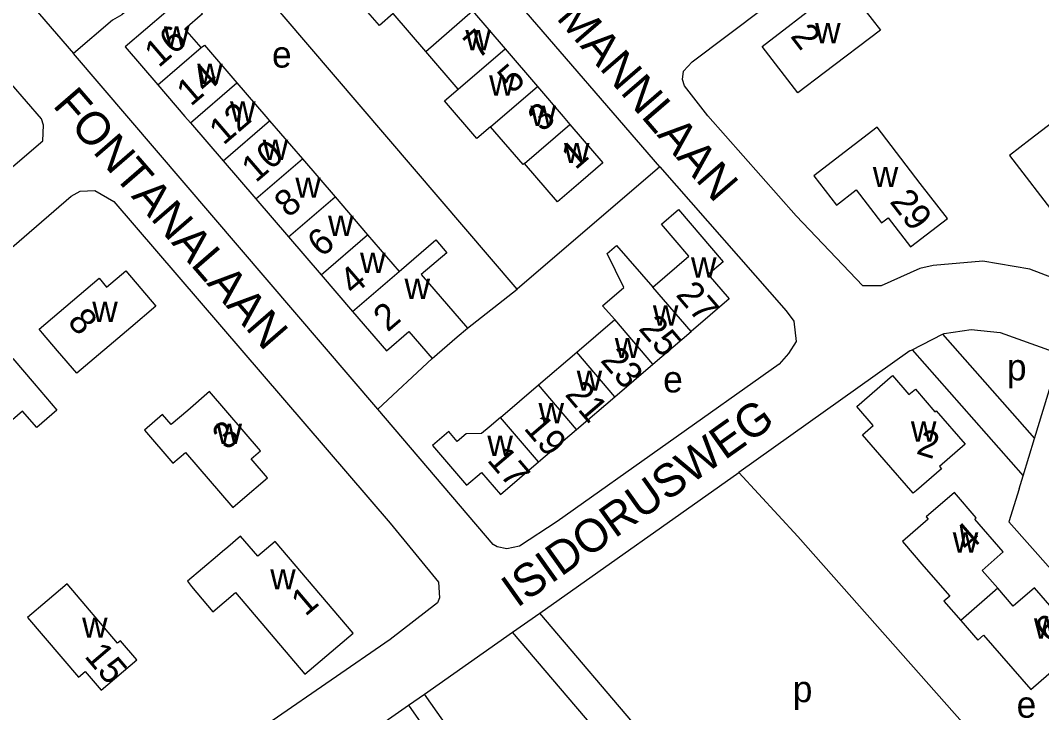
# Model space of a CAD drawing. Extents: x 158848 to 160613, y 385889 to 387762.
# Drawn here: x 160125.8 to 160280.6, y 386409.7 to 386514.5 of the extents above; entities that cross this region are included whole.
import ezdxf

# ---------------------------------------------------------------- set-up
doc = ezdxf.new("R2010")
doc.units = 0
for name, color, linetype in [('BLT_Basislijn', 7, 'Continuous'), ('BLT_Bebouwing', 7, 'Continuous'), ('BLT_Centroide', 7, 'Continuous'), ('BLT_Huisnummer', 7, 'Continuous'), ('BLT_Huisnummer_ tussenligend', 7, 'Continuous'), ('BLT_Onderverdeling_panden', 7, 'Continuous'), ('BLT_Straatnaam', 7, 'Continuous')]:
    doc.layers.add(name, color=color, linetype=linetype)

msp = doc.modelspace()

# ---------------------------------------------------------------- linework, layer by layer
at = {"layer": 'BLT_Basislijn'}
for p, q in [((160222.72, 386492.35), (160176.56, 386545.83)), ((160179.96, 386455.61), (160133.83, 386509.51)), ((160222.72, 386492.35), (160201.1, 386473.82)), ((160193.55, 386467.9), (160201.1, 386473.82)), ((160260.99, 386464.63), (160265.58, 386466.98)), ((160265.58, 386466.98), (160279.5, 386451.16)), ((160260.64, 386464.45), (160234.68, 386446.05)), ((160260.64, 386464.45), (160260.99, 386464.63)), ((160260.99, 386464.63), (160277.77, 386445.55)), ((160279.5, 386451.16), (160283.46, 386464.06)), ((160179.96, 386455.61), (160188.21, 386463.31)), ((160277.77, 386445.55), (160279.5, 386451.16)), ((160204.52, 386424.72), (160234.68, 386446.05)), ((160277.17, 386443.58), (160277.77, 386445.55)), ((160200.41, 386421.83), (160204.52, 386424.72)), ((160240.32, 386382.7), (160204.52, 386424.72)), ((160187.08, 386412.45), (160200.41, 386421.83)), ((160223.92, 386394.23), (160200.41, 386421.83)), ((160184.65, 386410.75), (160187.08, 386412.45)), ((160202.7, 386390.09), (160187.08, 386412.45))]:
    msp.add_line(p, q, dxfattribs=at)
for points in [[(160120.89, 386570.12), (160101.88, 386553.46), (160100.45, 386551.77), (160100.03, 386549.96), (160100.67, 386547.91), (160133.83, 386509.51)], [(160291.89, 386471.85), (160278.78, 386476.83), (160271.68, 386478.05), (160264.14, 386477.42), (160262.14, 386476.94), (160256.25, 386474.33), (160253.47, 386474.34), (160243.41, 386484.93), (160230, 386500.07), (160226.45, 386504.62), (160226.14, 386505.57), (160226.29, 386506.86), (160227.62, 386508.28), (160287.18, 386553.11)], [(160154.97, 386527.31), (160141.19, 386515.39), (160139.77, 386514.56), (160133.83, 386509.51)], [(160201.1, 386473.82), (160161.59, 386520.04), (160154.97, 386527.31)], [(160090.05, 386462.8), (160129.22, 386496.31), (160129.31, 386498.66), (160128.99, 386499.61), (160115.32, 386515.4), (160111.36, 386520.11)], [(160222.72, 386492.35), (160241.87, 386470.51), (160243.05, 386468.98), (160243.37, 386465.9), (160242.25, 386464.05), (160240.82, 386462.46), (160207.18, 386438.61), (160201.46, 386434.85), (160199.52, 386434.46), (160198.09, 386434.78), (160197.46, 386435.13), (160179.96, 386455.61)], [(160083.46, 386406.29), (160065.04, 386425.4), (160064.88, 386426.78), (160065.3, 386428.7), (160072.32, 386435), (160133.52, 386487.91), (160134.87, 386488.67), (160137.1, 386488.79), (160139.96, 386487.11), (160181.86, 386438.35)], [(160265.58, 386466.98), (160265.83, 386467.11), (160269.93, 386467.71), (160274.33, 386467.27), (160282.34, 386464.35)], [(160234.68, 386446.05), (160243.66, 386436.33), (160288.41, 386385.75), (160293.49, 386388.23), (160363.35, 386429.34), (160366.05, 386430.61), (160366.24, 386431.5), (160361.33, 386438.63)], [(160277.17, 386443.58), (160275.64, 386438.58), (160294.29, 386417.49)], [(160181.86, 386438.35), (160189.18, 386429.42), (160189.32, 386427.02), (160189.05, 386426.3), (160181.86, 386420.71), (160155.01, 386402.26)], [(160151.21, 386391.64), (160158, 386392.88), (160161.61, 386394.66), (160184.65, 386410.75)], [(160184.65, 386410.75), (160188.99, 386404.56)]]:
    msp.add_lwpolyline(points, dxfattribs=at)
at = {"layer": 'BLT_Bebouwing'}
for p, q in [((160187.24, 386509.85), (160182.31, 386515.6)), ((160194.31, 386515.98), (160199.26, 386510.23)), ((160199.26, 386510.23), (160204.17, 386504.51)), ((160192.16, 386504.13), (160187.24, 386509.85)), ((160151.58, 386499.03), (160156.54, 386493.27)), ((160163.58, 386499.32), (160168.54, 386493.56)), ((160156.54, 386493.27), (160161.49, 386487.5)), ((160168.54, 386493.56), (160173.49, 386487.8)), ((160161.49, 386487.5), (160166.44, 386481.74)), ((160173.49, 386487.8), (160178.44, 386482.04)), ((160178.44, 386482.04), (160183.19, 386476.51)), ((160166.44, 386481.74), (160171.39, 386475.98)), ((160171.39, 386475.98), (160176.14, 386470.45)), ((160210.12, 386464.26), (160215.9, 386469.2)), ((160221.67, 386462.46), (160227.45, 386467.4)), ((160204.35, 386459.31), (160210.12, 386464.26)), ((160215.89, 386457.52), (160221.67, 386462.46)), ((160198.57, 386454.37), (160204.35, 386459.31)), ((160210.11, 386452.57), (160215.89, 386457.52)), ((160204.33, 386447.63), (160210.11, 386452.57))]:
    msp.add_line(p, q, dxfattribs=at)
for points in [[(160182.31, 386515.6), (160180.21, 386513.75), (160175.29, 386519.47), (160177.36, 386521.35)], [(160153.2, 386510.43), (160150.74, 386513.29), (160153.41, 386515.58), (160150.91, 386518.48), (160141.68, 386510.55), (160146.63, 386504.79)], [(160247.67, 386517.9), (160248.86, 386516.36), (160251.83, 386518.66), (160254.89, 386514.7), (160256.17, 386513.04), (160247.63, 386506.58), (160243.65, 386503.56), (160238.21, 386510.59), (160247.67, 386517.9)], [(160153.2, 386510.43), (160153.71, 386510.81), (160158.63, 386505.08)], [(160146.63, 386504.79), (160150.75, 386500), (160151.58, 386499.03)], [(160158.63, 386505.08), (160163, 386500), (160163.58, 386499.32)], [(160197.08, 386498.41), (160195.01, 386496.64), (160190.1, 386502.36), (160192.16, 386504.13)], [(160204.17, 386504.51), (160208.05, 386500), (160209.09, 386498.79)], [(160282.95, 386484.7), (160283.93, 386485.46), (160286.25, 386482.45), (160291.83, 386486.74), (160288.78, 386490.7), (160282.29, 386499.13), (160278.83, 386496.47), (160275.73, 386494.08), (160282.95, 386484.7)], [(160202.19, 386492.86), (160201.99, 386492.69), (160197.08, 386498.41)], [(160209.09, 386498.79), (160214.1, 386492.96), (160210.73, 386490.06), (160207.22, 386487.05), (160202.19, 386492.86)], [(160266.31, 386484.52), (160262.2, 386489.84), (160255.64, 386498.35), (160252.17, 386495.67), (160246.07, 386490.97), (160249.49, 386486.53), (160252.5, 386488.85), (160256.34, 386483.88)], [(160221.68, 386474.14), (160227.14, 386478.81), (160222.98, 386483.68), (160225.57, 386485.9), (160232.34, 386477.98), (160230.07, 386476.03), (160233.23, 386472.34), (160227.45, 386467.4)], [(160256.34, 386483.88), (160257.32, 386484.64), (160260.73, 386480.22), (160266.31, 386484.52)], [(160183.19, 386476.51), (160188.75, 386481.3), (160190.43, 386479.34), (160186.57, 386476.02), (160193.55, 386467.9)], [(160215.9, 386469.2), (160214.05, 386471.29), (160217.28, 386474.05), (160214.76, 386479.21), (160216.18, 386480.42), (160221.68, 386474.14)], [(160137.73, 386475.47), (160138.88, 386474.12), (160141.79, 386476.59), (160146.33, 386471.26), (160142.52, 386468.02), (160134.35, 386461.07), (160131.44, 386464.49), (160129.18, 386467.14), (160128.66, 386467.75), (160137.73, 386475.47)], [(160176.14, 386470.45), (160181.29, 386464.46), (160184.7, 386467.39), (160188.21, 386463.31)], [(160188.21, 386463.31), (160192, 386466.57), (160193.55, 386467.9)], [(160120.59, 386462.21), (160121.77, 386460.83), (160124.64, 386463.29), (160127.89, 386459.5), (160131.35, 386455.46), (160128.29, 386452.83), (160126.15, 386455.32), (160117.37, 386447.79), (160114.44, 386451.21), (160111.61, 386454.52), (160120.59, 386462.21)], [(160261.62, 386443.32), (160261.13, 386442.89), (160256.72, 386447.96), (160253.44, 386451.73), (160255.06, 386453.14), (160252.57, 386456.01), (160258, 386460.72), (160260.48, 386457.86), (160261.46, 386458.65), (160264.4, 386455.22), (160264.61, 386455.39), (160268.99, 386450.32), (160265.1, 386446.94), (160265.4, 386446.6), (160261.62, 386443.32)], [(160158.01, 386440.71), (160159.46, 386441.97), (160163.25, 386445.23), (160160.77, 386448.11), (160162.2, 386449.34), (160154.48, 386458.31), (160151.16, 386455.45), (160148.66, 386453.3), (160147.36, 386454.81), (160144.62, 386452.45), (160148.93, 386447.44), (160150.82, 386449.07), (160158.01, 386440.71)], [(160198.57, 386454.37), (160196.85, 386452.91), (160195.7, 386451.92), (160193.37, 386451.9), (160192.02, 386450.75), (160190.75, 386452.24), (160188.26, 386450.11), (160193.4, 386444.1), (160195.68, 386446.05), (160198.55, 386442.68), (160204.33, 386447.63)], [(160273.95, 386428.48), (160271.59, 386431.2), (160274.78, 386433.99), (160270.47, 386438.96), (160270.69, 386439.16), (160267.36, 386443.01), (160263.08, 386439.29), (160263.38, 386438.95), (160259.48, 386435.57), (160262.76, 386431.8), (160266.68, 386427.29), (160265.79, 386426.52), (160268.32, 386423.6)], [(160164.41, 386435.6), (160161.77, 386433.36), (160159.19, 386436.39), (160157.23, 386434.73), (160156.42, 386434.04), (160155.66, 386433.4), (160151.11, 386429.54), (160151.73, 386428.76), (160154.97, 386424.94), (160158.4, 386427.86), (160168.92, 386415.47), (160176.23, 386421.67), (160164.41, 386435.6)], [(160134.59, 386415.02), (160135.61, 386415.88), (160138.04, 386413.03), (160143.44, 386417.64), (160140.97, 386420.53), (160140.54, 386420.16), (160132.87, 386429.15), (160129.87, 386426.58), (160126.89, 386424.04), (160134.59, 386415.02)], [(160268.32, 386423.6), (160270.9, 386420.63), (160271.79, 386421.4), (160278.95, 386413.16), (160282.84, 386416.54), (160283.14, 386416.2), (160283.64, 386416.64), (160287.42, 386419.91), (160284.03, 386423.75), (160283.85, 386423.55), (160279.5, 386428.55), (160276.3, 386425.77), (160273.95, 386428.48)]]:
    msp.add_lwpolyline(points, dxfattribs=at)
at = {"layer": 'BLT_Onderverdeling_panden'}
for p, q in [((160187.24, 386509.85), (160194.31, 386515.98)), ((160146.63, 386504.79), (160153.2, 386510.43)), ((160192.16, 386504.13), (160199.26, 386510.23)), ((160151.58, 386499.03), (160158.63, 386505.08)), ((160197.08, 386498.41), (160204.17, 386504.51)), ((160156.54, 386493.27), (160163.58, 386499.32)), ((160202.19, 386492.86), (160209.09, 386498.79)), ((160161.49, 386487.5), (160168.54, 386493.56)), ((160166.44, 386481.74), (160173.49, 386487.8)), ((160171.39, 386475.98), (160178.44, 386482.04)), ((160176.14, 386470.45), (160183.19, 386476.51)), ((160227.45, 386467.4), (160221.68, 386474.14)), ((160221.67, 386462.46), (160215.9, 386469.2)), ((160215.89, 386457.52), (160210.12, 386464.26)), ((160210.11, 386452.57), (160204.35, 386459.31)), ((160204.33, 386447.63), (160198.57, 386454.37)), ((160273.95, 386428.48), (160268.32, 386423.6))]:
    msp.add_line(p, q, dxfattribs=at)

# ---------------------------------------------------------------- texts
at = {"layer": 'BLT_Centroide'}
for s, p in [('w', (160147.55, 386510.58)), ('w', (160193.25, 386510.03)), ('w', (160246.26, 386511.09)), ('e', (160163.94, 386507.39)), ('w', (160152.61, 386504.91)), ('w', (160196.85, 386503.16)), ('w', (160157.58, 386499.19)), ('w', (160203.12, 386498.53)), ('w', (160162.53, 386493.41)), ('w', (160208.2, 386492.91)), ('w', (160255, 386489.28)), ('w', (160167.48, 386487.66)), ('w', (160172.44, 386481.88)), ('w', (160177.29, 386476.25)), ('w', (160227.45, 386475.55)), ('w', (160184.03, 386472.31)), ('w', (160136.7, 386468.84)), ('w', (160221.67, 386468.3)), ('w', (160215.89, 386463.36)), ('p', (160275.33, 386459.99)), ('w', (160210.12, 386458.41)), ('e', (160223.23, 386458.17)), ('w', (160204.34, 386453.47)), ('w', (160155.53, 386450.34)), ('w', (160260.78, 386450.69)), ('w', (160196.59, 386448.53)), ('w', (160267.12, 386433.89)), ('w', (160163.67, 386428.31)), ('w', (160135.16, 386420.98)), ('w', (160279.43, 386420.84)), ('p', (160242.87, 386411.23)), ('e', (160276.8, 386408.87))]:
    msp.add_text(s, height=4, dxfattribs=at).set_placement(p)
at = {"layer": 'BLT_Huisnummer'}
for s, rotation, p in [('16', 40.6607, (160146.77, 386507.28)), ('2', 307.681, (160242.4, 386512.12)), ('5', 40.6838, (160200.32, 386503.33)), ('10', 40.6607, (160161.49, 386489.85)), ('1', 40.6838, (160209.94, 386491.8)), ('29', 307.6542, (160257.45, 386487.05)), ('6', 40.6607, (160171.47, 386478.52)), ('27', 310.5424, (160225.02, 386472.9)), ('2', 40.6607, (160181.47, 386467.21)), ('8', 310.8221, (160132.81, 386468.8)), ('21', 310.5424, (160208.22, 386457.8)), ('3', 40.7331, (160157.07, 386449.28)), ('2', 342.5367, (160261.44, 386448.93)), ('17', 310.5424, (160196.42, 386447.86)), ('4', 40.9183, (160269.43, 386433.83)), ('1', 40.2999, (160169, 386424.13)), ('6', 40.9693, (160281.79, 386419.96)), ('15', 310.4887, (160135.39, 386418.15))]:
    msp.add_text(s, height=4, rotation=rotation, dxfattribs=at).set_placement(p)
at = {"layer": 'BLT_Huisnummer_ tussenligend'}
for s, rotation, p in [('7', 40.6838, (160195.18, 386508.56)), ('14', 40.6607, (160151.64, 386501.41)), ('12', 40.6607, (160156.58, 386495.53)), ('3', 40.6838, (160204.89, 386497.5)), ('8', 40.6607, (160166.45, 386484.52)), ('4', 40.6607, (160176.32, 386472.77)), ('25', 310.5424, (160219.38, 386467.78)), ('23', 310.5424, (160213.6, 386462.96)), ('19', 310.5424, (160201.99, 386452.68))]:
    msp.add_text(s, height=4, rotation=rotation, dxfattribs=at).set_placement(p)
at = {"layer": 'BLT_Straatnaam'}
for s, rotation, p in [('NEUMANNLAAN', 310.7694, (160197.69, 386525.55)), ('FONTANALAAN', 310.9192, (160130.58, 386501.61)), ('ISIDORUSWEG', 35.4218, (160201.08, 386425.44))]:
    msp.add_text(s, height=5, rotation=rotation, dxfattribs=at).set_placement(p)

doc.saveas('drawing.dxf')
